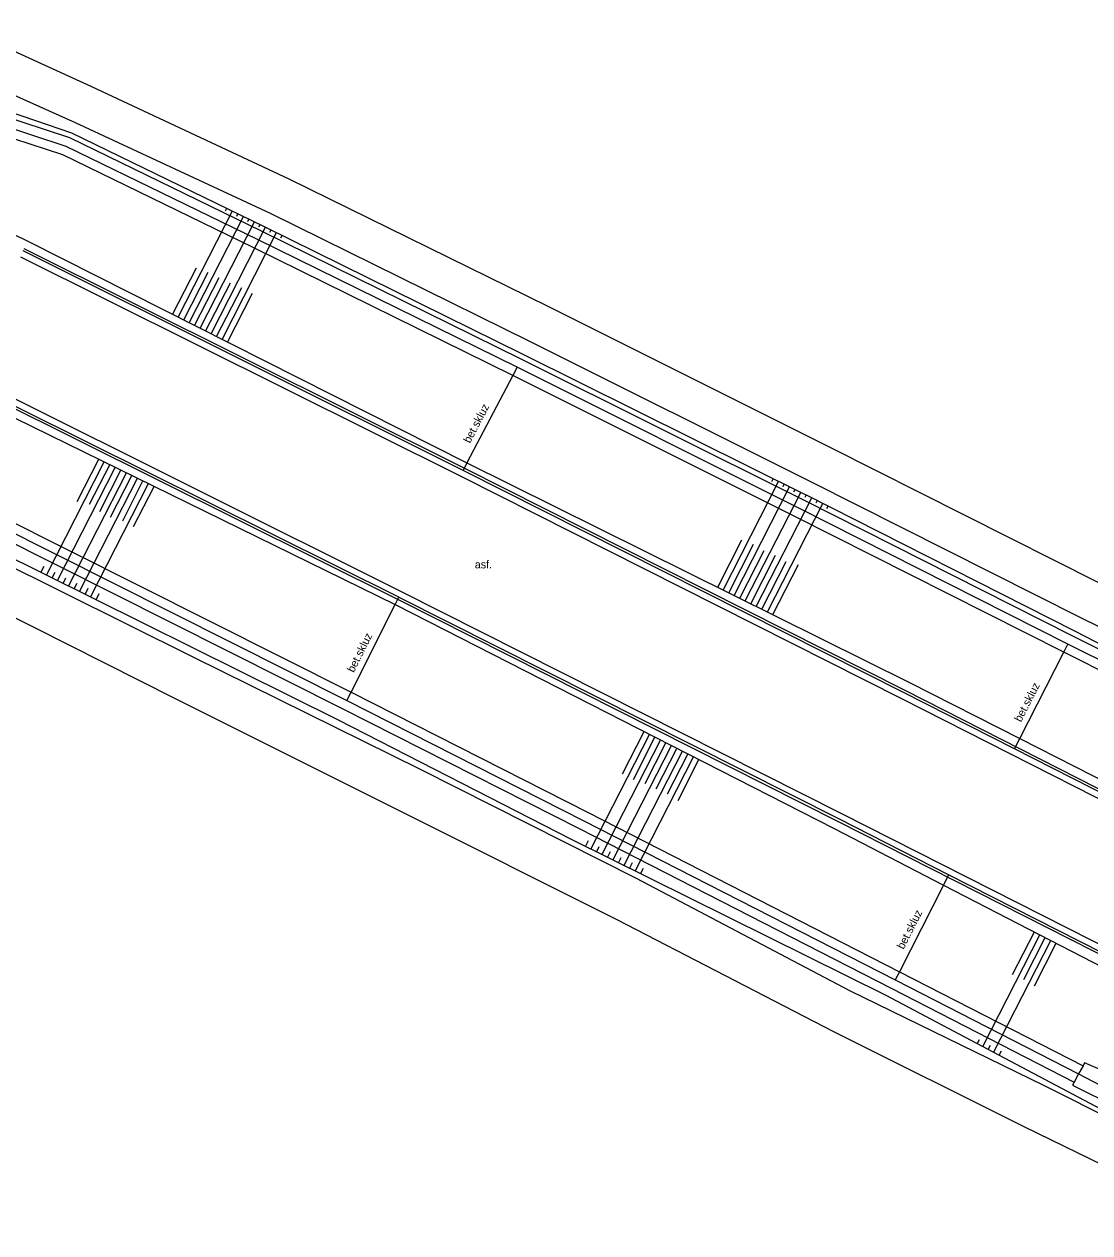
# Model space of a CAD drawing. Extents: x -539244 to -537359, y -1183785 to -1181851.
# Drawn here: x -538560.9 to -538474.3, y -1182845.5 to -1182747.3 of the extents above; entities that cross this region are included whole.
import ezdxf

# ---------------------------------------------------------------- set-up
doc = ezdxf.new("R2010")
doc.units = 0
for name, color, linetype in [('Vrstva 10', 7, 'Continuous'), ('Vrstva 11', 7, 'Continuous'), ('Vrstva 14', 7, 'Continuous'), ('Vrstva 15', 7, 'Continuous'), ('Vrstva 40', 7, 'Continuous'), ('Vrstva 9', 7, 'Continuous')]:
    doc.layers.add(name, color=color, linetype=linetype)

msp = doc.modelspace()

# ---------------------------------------------------------------- linework, layer by layer
at = {"layer": 'Vrstva 10'}
for p, q in [((-538561.169, -1182766.183), (-538525.361, -1182784.039)), ((-538530.209, -1182793.399), (-538565.856, -1182775.604)), ((-538525.361, -1182784.039), (-538489.631, -1182802.063)), ((-538494.407, -1182811.446), (-538530.209, -1182793.399)), ((-538489.631, -1182802.063), (-538453.977, -1182820.153)), ((-538458.743, -1182829.553), (-538494.407, -1182811.446))]:
    msp.add_line(p, q, dxfattribs=at)
at = {"layer": 'Vrstva 11'}
for p, q in [((-538564.03, -1182748.422), (-538555.397, -1182752.339)), ((-538556.704, -1182755.307), (-538565.433, -1182751.382)), ((-538555.397, -1182752.339), (-538539.378, -1182759.854)), ((-538557.163, -1182756.515), (-538566.543, -1182753.454)), ((-538557.727, -1182757.909), (-538567.086, -1182754.855)), ((-538540.847, -1182762.664), (-538556.704, -1182755.307)), ((-538541.594, -1182764.093), (-538557.163, -1182756.515)), ((-538542.254, -1182765.441), (-538557.727, -1182757.909)), ((-538539.378, -1182759.854), (-538518.346, -1182770.203)), ((-538519.812, -1182773.063), (-538540.847, -1182762.664)), ((-538520.509, -1182774.487), (-538541.594, -1182764.093)), ((-538521.177, -1182775.831), (-538542.254, -1182765.441)), ((-538518.346, -1182770.203), (-538495.381, -1182781.683)), ((-538496.867, -1182784.51), (-538519.812, -1182773.063)), ((-538497.56, -1182785.961), (-538520.509, -1182774.487)), ((-538498.234, -1182787.301), (-538521.177, -1182775.831)), ((-538495.381, -1182781.683), (-538473.693, -1182792.597)), ((-538569.658, -1182783.79), (-538534.312, -1182801.546)), ((-538489.405, -1182801.595), (-538525.17, -1182783.553)), ((-538475.061, -1182795.493), (-538496.867, -1182784.51)), ((-538570.426, -1182785.082), (-538534.988, -1182802.884)), ((-538475.768, -1182796.967), (-538497.56, -1182785.961)), ((-538476.446, -1182798.305), (-538498.234, -1182787.301)), ((-538547.134, -1182798.688), (-538565.397, -1182789.61)), ((-538566.909, -1182792.814), (-538548.597, -1182802.06)), ((-538494.666, -1182811.861), (-538530.407, -1182793.84)), ((-538457.128, -1182804.455), (-538475.061, -1182795.493)), ((-538460.885, -1182804.439), (-538475.768, -1182796.967)), ((-538528.685, -1182807.817), (-538547.134, -1182798.688)), ((-538461.569, -1182805.774), (-538476.446, -1182798.305)), ((-538534.312, -1182801.546), (-538515.07, -1182811.315)), ((-538548.597, -1182802.06), (-538530.422, -1182811.155)), ((-538534.988, -1182802.884), (-538515.752, -1182812.651)), ((-538511.145, -1182816.664), (-538528.685, -1182807.817)), ((-538530.422, -1182811.155), (-538512.74, -1182820)), ((-538515.07, -1182811.315), (-538489.789, -1182824.247)), ((-538515.752, -1182812.651), (-538490.473, -1182825.583)), ((-538493.805, -1182825.798), (-538511.145, -1182816.664)), ((-538512.74, -1182820), (-538495.14, -1182829.097)), ((-538489.789, -1182824.247), (-538474.883, -1182831.882)), ((-538477.999, -1182833.509), (-538493.805, -1182825.798)), ((-538490.473, -1182825.583), (-538475.592, -1182833.205)), ((-538495.14, -1182829.097), (-538479.69, -1182836.826)), ((-538472.667, -1182832.544), (-538474.756, -1182831.645)), ((-538460.441, -1182842.376), (-538477.999, -1182833.509)), ((-538475.727, -1182833.456), (-538469.918, -1182836.378)), ((-538479.69, -1182836.826), (-538461.985, -1182845.451))]:
    msp.add_line(p, q, dxfattribs=at)
for points in [[(-538525.17, -1182783.553), (-538525.226, -1182783.525), (-538560.949, -1182765.709)], [(-538530.407, -1182793.84), (-538530.442, -1182793.823), (-538566.153, -1182776.067)], [(-538453.722, -1182819.731), (-538480.448, -1182806.147), (-538489.405, -1182801.595)], [(-538459.1, -1182829.941), (-538485.794, -1182816.371), (-538494.666, -1182811.861)], [(-538474.756, -1182831.645), (-538474.883, -1182831.882), (-538475.264, -1182832.53), (-538475.592, -1182833.205), (-538475.727, -1182833.456)]]:
    msp.add_lwpolyline(points, dxfattribs=at)
at = {"layer": 'Vrstva 14'}
for p, q in [((-538566.132, -1182753.011), (-538557.014, -1182756.114)), ((-538557.445, -1182757.212), (-538566.772, -1182754.168)), ((-538557.014, -1182756.114), (-538541.382, -1182763.714)), ((-538541.924, -1182764.767), (-538557.445, -1182757.212)), ((-538541.382, -1182763.714), (-538520.358, -1182774.095)), ((-538560.522, -1182764.953), (-538524.906, -1182782.915)), ((-538520.843, -1182775.159), (-538541.924, -1182764.767)), ((-538520.358, -1182774.095), (-538497.33, -1182785.555)), ((-538497.897, -1182786.631), (-538520.843, -1182775.159)), ((-538566.557, -1182776.872), (-538530.739, -1182794.415)), ((-538524.906, -1182782.915), (-538488.966, -1182800.758)), ((-538570.042, -1182784.436), (-538534.65, -1182802.215)), ((-538475.557, -1182796.594), (-538497.33, -1182785.555)), ((-538535.33, -1182803.807), (-538570.792, -1182786.215)), ((-538476.105, -1182797.637), (-538497.897, -1182786.631)), ((-538530.739, -1182794.415), (-538530.442, -1182793.823)), ((-538530.739, -1182794.415), (-538495.104, -1182812.627)), ((-538460.787, -1182804.249), (-538475.557, -1182796.594)), ((-538476.446, -1182798.305), (-538476.105, -1182797.637)), ((-538461.208, -1182805.116), (-538476.105, -1182797.637)), ((-538480.02, -1182805.308), (-538476.446, -1182798.305)), ((-538534.65, -1182802.215), (-538515.411, -1182811.983)), ((-538516.432, -1182813.519), (-538535.33, -1182803.807)), ((-538480.448, -1182806.147), (-538480.02, -1182805.308)), ((-538515.411, -1182811.983), (-538490.131, -1182824.915)), ((-538490.861, -1182826.18), (-538516.432, -1182813.519)), ((-538485.794, -1182816.371), (-538486.219, -1182817.21)), ((-538490.131, -1182824.915), (-538475.264, -1182832.53)), ((-538472.928, -1182835.682), (-538490.861, -1182826.18)), ((-538475.264, -1182832.53), (-538472.302, -1182834.08))]:
    msp.add_line(p, q, dxfattribs=at)
for points in [[(-538596.45, -1182747.29), (-538569.646, -1182760.467), (-538560.522, -1182764.953)], [(-538520.843, -1182775.159), (-538521.177, -1182775.831), (-538524.906, -1182782.915), (-538525.226, -1182783.525)], [(-538534.65, -1182802.215), (-538534.312, -1182801.546), (-538530.739, -1182794.415)], [(-538488.966, -1182800.758), (-538480.02, -1182805.308), (-538453.209, -1182818.943)], [(-538495.104, -1182812.627), (-538486.219, -1182817.21), (-538459.455, -1182831.015)], [(-538486.219, -1182817.21), (-538489.789, -1182824.247), (-538490.131, -1182824.915)]]:
    msp.add_lwpolyline(points, dxfattribs=at)
at = {"layer": 'Vrstva 15'}
for p, q in [((-538548.357, -1182771.088), (-538543.955, -1182762.463)), ((-538544.507, -1182762.443), (-538544.405, -1182762.244)), ((-538547.465, -1182771.538), (-538543.056, -1182762.9)), ((-538546.571, -1182771.989), (-538542.156, -1182763.338)), ((-538543.604, -1182762.874), (-538543.506, -1182762.681)), ((-538542.703, -1182763.31), (-538542.606, -1182763.119)), ((-538545.678, -1182772.439), (-538541.257, -1182763.776)), ((-538544.786, -1182772.889), (-538540.361, -1182764.218)), ((-538541.802, -1182763.742), (-538541.707, -1182763.556)), ((-538540.905, -1182764.186), (-538540.809, -1182763.997)), ((-538540.015, -1182764.641), (-538539.912, -1182764.44)), ((-538548.804, -1182770.863), (-538546.872, -1182767.077)), ((-538547.91, -1182771.313), (-538545.934, -1182767.441)), ((-538547.018, -1182771.764), (-538545.034, -1182767.877)), ((-538546.125, -1182772.214), (-538544.119, -1182768.284)), ((-538545.232, -1182772.664), (-538543.196, -1182768.674)), ((-538544.339, -1182773.114), (-538542.311, -1182769.14)), ((-538559.049, -1182792.04), (-538554.358, -1182782.847)), ((-538556.563, -1182786.068), (-538554.807, -1182782.627)), ((-538555.549, -1182786.281), (-538553.909, -1182783.067)), ((-538558.154, -1182792.484), (-538553.46, -1182783.287)), ((-538557.258, -1182792.929), (-538552.561, -1182783.727)), ((-538554.728, -1182786.874), (-538553.01, -1182783.507)), ((-538553.842, -1182787.335), (-538552.113, -1182783.946)), ((-538556.362, -1182793.374), (-538551.663, -1182784.167)), ((-538555.467, -1182793.818), (-538550.766, -1182784.606)), ((-538552.863, -1182787.615), (-538551.215, -1182784.386)), ((-538551.978, -1182788.083), (-538550.316, -1182784.827)), ((-538504.099, -1182793.245), (-538499.598, -1182784.426)), ((-538503.204, -1182793.689), (-538498.704, -1182784.871)), ((-538500.162, -1182784.428), (-538500.047, -1182784.203)), ((-538499.242, -1182784.827), (-538499.151, -1182784.649)), ((-538502.308, -1182794.134), (-538497.808, -1182785.317)), ((-538501.412, -1182794.579), (-538496.914, -1182785.766)), ((-538498.353, -1182785.284), (-538498.256, -1182785.094)), ((-538497.445, -1182785.705), (-538497.361, -1182785.54)), ((-538496.551, -1182786.155), (-538496.468, -1182785.992)), ((-538500.517, -1182795.023), (-538496.023, -1182786.218)), ((-538495.676, -1182786.638), (-538495.577, -1182786.444)), ((-538504.548, -1182793.022), (-538502.586, -1182789.177)), ((-538503.652, -1182793.467), (-538501.642, -1182789.529)), ((-538502.756, -1182793.912), (-538500.777, -1182790.034)), ((-538501.86, -1182794.356), (-538499.844, -1182790.405)), ((-538500.964, -1182794.801), (-538498.985, -1182790.924)), ((-538559.498, -1182791.818), (-538559.24, -1182791.313)), ((-538558.601, -1182792.263), (-538558.356, -1182791.782)), ((-538500.07, -1182795.245), (-538497.992, -1182791.175)), ((-538557.706, -1182792.707), (-538557.48, -1182792.265)), ((-538556.81, -1182793.151), (-538556.568, -1182792.677)), ((-538555.914, -1182793.596), (-538555.658, -1182793.094)), ((-538555.018, -1182794.04), (-538554.759, -1182793.533)), ((-538514.847, -1182814.304), (-538510.084, -1182804.971)), ((-538513.951, -1182814.747), (-538509.194, -1182805.426)), ((-538512.28, -1182808.176), (-538510.529, -1182804.744)), ((-538511.388, -1182808.626), (-538509.639, -1182805.199)), ((-538510.43, -1182808.95), (-538508.748, -1182805.654)), ((-538513.054, -1182815.191), (-538508.303, -1182805.881)), ((-538512.157, -1182815.635), (-538507.412, -1182806.337)), ((-538509.54, -1182809.404), (-538507.858, -1182806.109)), ((-538508.618, -1182809.799), (-538506.967, -1182806.564)), ((-538511.262, -1182816.079), (-538506.522, -1182806.791)), ((-538507.77, -1182810.336), (-538506.077, -1182807.018)), ((-538515.295, -1182814.082), (-538515.041, -1182813.584)), ((-538514.399, -1182814.526), (-538514.168, -1182814.073)), ((-538513.502, -1182814.97), (-538513.255, -1182814.485)), ((-538512.606, -1182815.413), (-538512.376, -1182814.961)), ((-538511.71, -1182815.857), (-538511.461, -1182815.368)), ((-538510.817, -1182816.306), (-538510.581, -1182815.844)), ((-538483.027, -1182830.331), (-538478.391, -1182821.248)), ((-538480.599, -1182824.47), (-538478.837, -1182821.018)), ((-538482.144, -1182830.799), (-538477.503, -1182821.706)), ((-538479.683, -1182824.879), (-538477.947, -1182821.477)), ((-538478.823, -1182825.393), (-538477.058, -1182821.935)), ((-538483.469, -1182830.097), (-538483.286, -1182829.737)), ((-538482.585, -1182830.565), (-538482.403, -1182830.208)), ((-538481.701, -1182831.034), (-538481.509, -1182830.658))]:
    msp.add_line(p, q, dxfattribs=at)
at = {"layer": 'Vrstva 9'}
for p, q in [((-538525.081, -1182783.374), (-538560.86, -1182765.53)), ((-538566.242, -1182776.246), (-538530.497, -1182794.019)), ((-538489.315, -1182801.416), (-538525.08, -1182783.374)), ((-538530.497, -1182794.019), (-538494.757, -1182812.039)), ((-538453.631, -1182819.553), (-538489.321, -1182801.413)), ((-538494.757, -1182812.039), (-538459.191, -1182830.119))]:
    msp.add_line(p, q, dxfattribs=at)

# ---------------------------------------------------------------- texts
at = {"layer": 'Vrstva 40'}
for rotation, p in [(62.34968, (-538524.665, -1182781.375)), (63.36944, (-538534.099, -1182799.999)), (62.96293, (-538479.923, -1182804.018)), (63.0873, (-538489.455, -1182822.478))]:
    msp.add_text('bet.skluz', height=0.65, rotation=rotation, dxfattribs=at).set_placement(p)
msp.add_text('asf.', height=0.65, dxfattribs=at).set_placement((-538524.27, -1182791.49))

doc.saveas('drawing.dxf')
